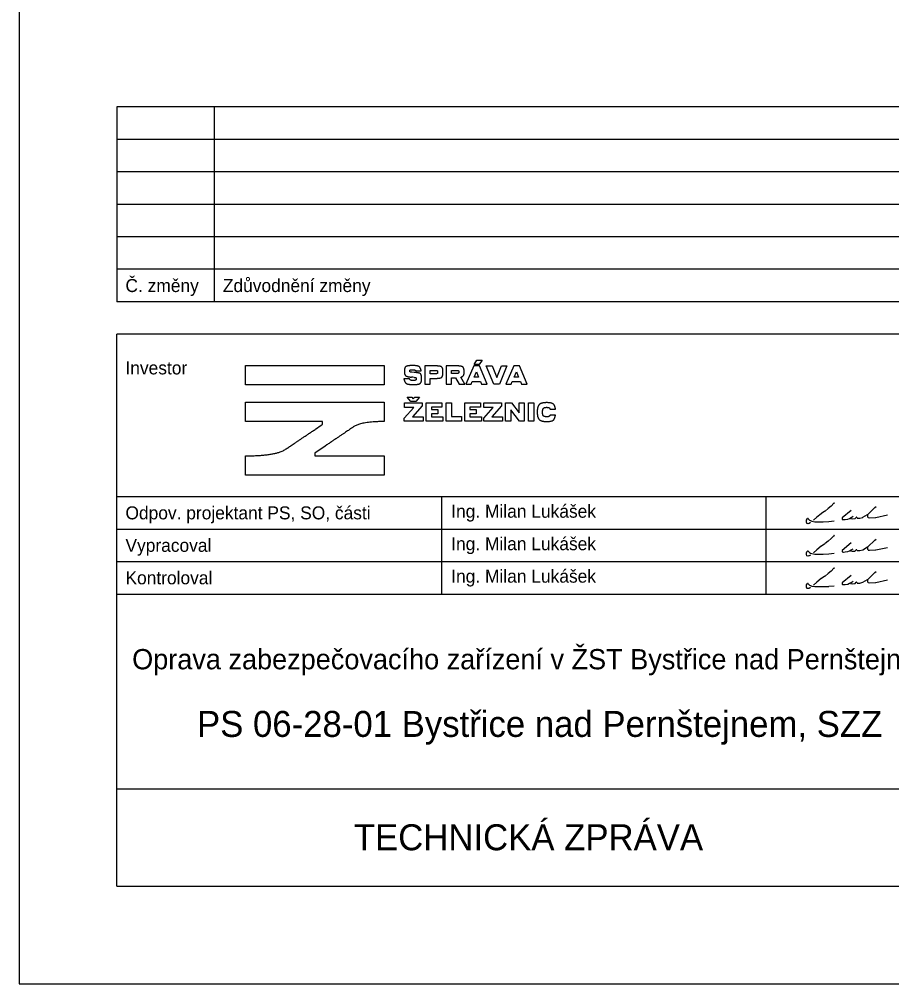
# Model space of a CAD drawing. Extents: x -790261 to -790051, y -987399 to -987102.
# Drawn here: x -790260.6 to -790126.2, y -987398.6 to -987250.1 of the extents above; entities that cross this region are included whole.
import ezdxf

# ---------------------------------------------------------------- set-up
doc = ezdxf.new("R2010")
doc.units = 0
for name, color, linetype in [('Deska žb', 7, 'Continuous'), ('logo_sprava_zeleznic', 7, 'Continuous'), ('Nová vrstva (0)', 7, 'Continuous'), ('Ramečky', 7, 'Continuous'), ('Rámečky-tisk', 7, 'Continuous'), ('Text', 7, 'Continuous'), ('Text barevný', 7, 'Continuous')]:
    doc.layers.add(name, color=color, linetype=linetype)

# ---------------------------------------------------------------- blocks, each defined once
blk = doc.blocks.new('Lukášek')
at = {"layer": 'Deska žb'}
for points in [[(-800, 511), (-947, 387)], [(-658, 623), (-799, 512)], [(-538, 757), (-656, 625)], [(-526, 763), (-532, 761)], [(-502, 743), (-503, 750)], [(1060, 236), (1392, 554)], [(1393, 555), (1452, 601)], [(-1810, -20), (-1764, 37)], [(-1741, 39), (-1734, 34)], [(-1733, 32), (-1676, -31)], [(-1334, 99), (-1493, -40)], [(-1120, 270), (-1334, 99)], [(-949, 386), (-1119, 271)], [(-146, 58), (-146, 41)], [(-146, 38), (-141, 12)], [(277, 422), (-140, 71)], [(0, 0), (116, 16)], [(120, 17), (203, 49)], [(205, 50), (283, 92)], [(244, 59), (250, 49)], [(261, 42), (331, 30)], [(284, 93), (373, 148)], [(335, 30), (465, 39)], [(476, 45), (519, 96)], [(546, 94), (559, 68)], [(574, 60), (681, 63)], [(685, 63), (829, 98)], [(833, 100), (1057, 233)], [(1056, 231), (1056, 130)], [(1058, 121), (1075, 95)], [(1086, 88), (1147, 79)], [(1150, 79), (1434, 92)], [(1437, 93), (1997, 211)], [(-1825, -119), (-1813, -28)], [(-1809, -179), (-1825, -126)], [(-1757, -200), (-1797, -190)], [(-1700, -189), (-1749, -201)], [(-1634, -152), (-1695, -187)], [(-1672, -34), (-1636, -56)], [(-1633, -57), (-1570, -82)], [(-1567, -83), (-1418, -106)], [(-1415, -106), (-1252, -106), (-1041, -106)], [(-1040, -106), (-770, -93)], [(-769, -92), (-512, -66)], [(-127, -2), (-88, -6)], [(-85, -7), (-1, 0)]]:
    blk.add_lwpolyline(points, dxfattribs=at)
for centre, start, end in [((-789, 499), 128.3333, 130.1792), ((-669, 636), 308.3333, 317.9357), ((-525, 746), 113.9625, 137.9357), ((-519, 748), 6.3402, 113.9625), ((1403, 542), 127.875, 133.8427), ((-1751, 26), 50.1944, 140.7106), ((-1745, 21), 41.9872, 50.1944), ((-1324, 86), 128.6598, 131.1859), ((-1110, 257), 123.9436, 128.6598), ((-958, 399), 303.9436, 310.1792), ((-129, 58), 130.156, 180), ((-129, 41), 180, 189.4623), ((-125, 15), 189.4623, 262.875), ((-2, 16), 274.3987, 277.9072), ((114, 32), 277.9072, 291.0375), ((197, 64), 291.0375, 298.4429), ((264, 58), 210.9638, 260.5377), ((275, 107), 298.4429, 302.1957), ((334, 46), 260.5377, 274.0856), ((463, 55), 274.0856, 320.4403), ((531, 86), 27.8973, 140.4403), ((574, 76), 207.8973, 271.5911), ((681, 79), 271.5911, 283.7363), ((825, 114), 283.7363, 300.7189), ((1072, 130), 180, 212.4712), ((1049, 247), 300.7189, 313.8427), ((1089, 104), 212.4712, 261.8699), ((1149, 96), 261.8699, 272.6324), ((1433, 109), 272.6324, 281.9566), ((-1809, -121), 172.4054, 196.6992), ((-1797, -30), 140.7106, 172.4054), ((-1793, -175), 196.6992, 255.9638), ((-1753, -184), 255.9638, 283.2405), ((-1703, -173), 283.2405, 300.0686), ((-1664, -20), 221.9872, 239.7436), ((-1627, -41), 239.7436, 248.1986), ((-1564, -67), 248.1986, 261.3475), ((-1415, -89), 261.3475, 270), ((-1041, -89), 270, 272.7927), ((-771, -76), 272.7927, 275.856), ((-86, 10), 262.875, 274.3987)]:
    blk.add_arc(centre, 16.5, start, end, dxfattribs=at)

msp = doc.modelspace()

# ---------------------------------------------------------------- linework, layer by layer
at = {"layer": 'logo_sprava_zeleznic'}
for p, q in [((-790190.56, -987303.26), (-790190.12, -987302.6)), ((-790189.78, -987303.26), (-790190.56, -987303.26)), ((-790190.12, -987302.6), (-790189.3, -987302.6)), ((-790189.3, -987302.6), (-790189.78, -987303.26)), ((-790188.7, -987303.48), (-790187.76, -987303.48)), ((-790187.49, -987306.29), (-790188.7, -987303.48)), ((-790187.76, -987303.48), (-790187.05, -987305.28)), ((-790187.05, -987305.28), (-790186.34, -987303.48)), ((-790185.49, -987303.48), (-790186.64, -987306.29)), ((-790186.34, -987303.48), (-790185.49, -987303.48)), ((-790199.76, -987304.48), (-790200.15, -987304.45)), ((-790199.51, -987304.23), (-790198.69, -987304.23)), ((-790200.51, -987305.45), (-790201.36, -987305.45)), ((-790186.64, -987306.29), (-790187.49, -987306.29)), ((-790201.26, -987309.17), (-790198.55, -987309.17)), ((-790201.26, -987309.86), (-790201.26, -987309.17)), ((-790200.29, -987308.96), (-790200.83, -987308.28)), ((-790200.83, -987308.28), (-790200.14, -987308.28)), ((-790199.53, -987308.96), (-790200.29, -987308.96)), ((-790200.14, -987308.28), (-790199.91, -987308.56)), ((-790198.55, -987309.63), (-790200.02, -987311.29)), ((-790199.91, -987308.56), (-790199.68, -987308.28)), ((-790199.68, -987308.28), (-790198.97, -987308.28)), ((-790198.97, -987308.28), (-790199.53, -987308.96)), ((-790198.55, -987309.17), (-790198.55, -987309.63)), ((-790197.92, -987309.17), (-790195.49, -987309.17)), ((-790197.92, -987311.99), (-790197.92, -987309.17)), ((-790195.49, -987309.17), (-790195.49, -987309.83)), ((-790194.86, -987309.17), (-790194.05, -987309.17)), ((-790194.86, -987311.99), (-790194.86, -987309.17)), ((-790194.05, -987309.17), (-790194.05, -987311.28)), ((-790191.99, -987309.17), (-790189.57, -987309.17)), ((-790191.99, -987311.99), (-790191.99, -987309.17)), ((-790189.57, -987309.17), (-790189.57, -987309.83)), ((-790189.03, -987309.17), (-790186.33, -987309.17)), ((-790189.03, -987309.86), (-790189.03, -987309.17)), ((-790186.33, -987309.63), (-790187.8, -987311.29)), ((-790186.33, -987309.17), (-790186.33, -987309.63)), ((-790185.69, -987309.17), (-790184.78, -987309.17)), ((-790185.69, -987311.99), (-790185.69, -987309.17)), ((-790184.78, -987309.17), (-790183.63, -987310.68)), ((-790183.63, -987310.68), (-790183.63, -987309.17)), ((-790183.63, -987309.17), (-790182.85, -987309.17)), ((-790182.85, -987309.17), (-790182.85, -987311.99)), ((-790201.3, -987311.53), (-790199.84, -987309.86)), ((-790199.84, -987309.86), (-790201.26, -987309.86)), ((-790195.49, -987309.83), (-790197.1, -987309.83)), ((-790197.1, -987309.83), (-790197.1, -987310.2)), ((-790197.1, -987310.2), (-790196.14, -987310.2)), ((-790196.14, -987310.87), (-790197.1, -987310.87)), ((-790197.1, -987310.87), (-790197.1, -987311.3)), ((-790196.14, -987310.2), (-790196.14, -987310.87)), ((-790189.57, -987309.83), (-790191.18, -987309.83)), ((-790191.18, -987309.83), (-790191.18, -987310.2)), ((-790191.18, -987310.2), (-790190.22, -987310.2)), ((-790190.22, -987310.87), (-790191.18, -987310.87)), ((-790191.18, -987310.87), (-790191.18, -987311.3)), ((-790190.22, -987310.2), (-790190.22, -987310.87)), ((-790189.07, -987311.53), (-790187.61, -987309.86)), ((-790187.61, -987309.86), (-790189.03, -987309.86)), ((-790183.53, -987311.99), (-790184.89, -987310.26)), ((-790184.89, -987310.26), (-790184.89, -987311.99)), ((-790178.84, -987310.12), (-790178.01, -987310.12)), ((-790178.01, -987311.05), (-790178.83, -987311.05)), ((-790201.3, -987311.99), (-790201.3, -987311.53)), ((-790198.39, -987311.99), (-790201.3, -987311.99)), ((-790200.02, -987311.29), (-790198.39, -987311.29)), ((-790198.39, -987311.29), (-790198.39, -987311.99)), ((-790195.34, -987311.99), (-790197.92, -987311.99)), ((-790197.1, -987311.3), (-790195.34, -987311.3)), ((-790195.34, -987311.3), (-790195.34, -987311.99)), ((-790192.47, -987311.99), (-790194.86, -987311.99)), ((-790194.05, -987311.28), (-790192.47, -987311.28)), ((-790192.47, -987311.28), (-790192.47, -987311.99)), ((-790189.41, -987311.99), (-790191.99, -987311.99)), ((-790191.18, -987311.3), (-790189.41, -987311.3)), ((-790189.41, -987311.3), (-790189.41, -987311.99)), ((-790189.07, -987311.99), (-790189.07, -987311.53)), ((-790186.16, -987311.99), (-790189.07, -987311.99)), ((-790187.8, -987311.29), (-790186.16, -987311.29)), ((-790186.16, -987311.29), (-790186.16, -987311.99)), ((-790184.89, -987311.99), (-790185.69, -987311.99)), ((-790182.85, -987311.99), (-790183.53, -987311.99))]:
    msp.add_line(p, q, dxfattribs=at)
for points in [[(-790225.73, -987303.4), (-790204.41, -987303.4), (-790204.41, -987306.38), (-790225.73, -987306.38)], [(-790191.8, -987306.29), (-790190.98, -987306.29), (-790190.82, -987305.89), (-790189.57, -987305.89), (-790189.41, -987306.29), (-790188.53, -987306.29), (-790189.73, -987303.48), (-790190.6, -987303.48)], [(-790185.65, -987306.29), (-790184.83, -987306.29), (-790184.66, -987305.89), (-790183.42, -987305.89), (-790183.26, -987306.29), (-790182.38, -987306.29), (-790183.57, -987303.48), (-790184.45, -987303.48)], [(-790190.19, -987304.39), (-790189.85, -987305.23), (-790190.54, -987305.23)], [(-790184.04, -987304.39), (-790183.7, -987305.23), (-790184.39, -987305.23)], [(-790182.16, -987309.17), (-790181.35, -987309.17), (-790181.35, -987311.99), (-790182.16, -987311.99)]]:
    msp.add_lwpolyline(points, close=True, dxfattribs=at)
for points in [[(-790196.38, -987303.48), (-790198.11, -987303.48), (-790198.11, -987306.29), (-790197.3, -987306.29), (-790197.3, -987305.39), (-790196.38, -987305.39)], [(-790193.12, -987303.48), (-790194.84, -987303.48), (-790194.84, -987306.29), (-790194.03, -987306.29), (-790194.03, -987305.31), (-790193.39, -987305.31), (-790192.84, -987306.29), (-790191.98, -987306.29), (-790192.59, -987305.22)], [(-790196.48, -987304.69), (-790197.3, -987304.69), (-790197.3, -987304.17), (-790196.48, -987304.17)], [(-790193.22, -987304.64), (-790194.03, -987304.64), (-790194.03, -987304.16), (-790193.22, -987304.16)], [(-790213.87, -987312.46), (-790213.87, -987312.04), (-790225.73, -987312.04), (-790225.73, -987309.07), (-790204.41, -987309.07), (-790204.41, -987312.04)], [(-790215.1, -987316.91), (-790215.1, -987317.32), (-790204.41, -987317.32), (-790204.41, -987320.3), (-790225.73, -987320.3), (-790225.73, -987317.32), (-790225.71, -987317.32)]]:
    msp.add_lwpolyline(points, dxfattribs=at)
for centre, radius, start, end in [((-790201.9, -987326.14), 21.01, 84.2634, 85.3384), ((-790251.18, -987259.6), 64.69, 304.0901, 305.2133), ((-789914.63, -987753.54), 530.02, 124.292, 124.5333)]:
    msp.add_arc(centre, radius, start, end, dxfattribs=at)
for points in [[(-790200.05, -987303.42), (-790200.77, -987303.42), (-790201.29, -987303.71), (-790201.29, -987304.28)], [(-790198.69, -987304.23), (-790198.77, -987303.87), (-790199.09, -987303.42), (-790200.05, -987303.42)], [(-790195.34, -987304.43), (-790195.34, -987303.8), (-790195.73, -987303.48), (-790196.38, -987303.48)], [(-790192.08, -987304.4), (-790192.08, -987303.79), (-790192.49, -987303.48), (-790193.12, -987303.48)], [(-790201.29, -987304.28), (-790201.29, -987304.83), (-790200.87, -987305.14), (-790200.19, -987305.2)], [(-790200.46, -987304.24), (-790200.46, -987304.12), (-790200.3, -987304.06), (-790200.05, -987304.06)], [(-790200.15, -987304.45), (-790200.35, -987304.43), (-790200.46, -987304.36), (-790200.46, -987304.24)], [(-790200.05, -987304.06), (-790199.73, -987304.06), (-790199.55, -987304.17), (-790199.51, -987304.23)], [(-790198.63, -987305.4), (-790198.63, -987304.79), (-790199.03, -987304.53), (-790199.76, -987304.48)], [(-790196.48, -987304.17), (-790196.27, -987304.17), (-790196.17, -987304.26), (-790196.17, -987304.43)], [(-790196.17, -987304.43), (-790196.17, -987304.59), (-790196.27, -987304.69), (-790196.48, -987304.69)], [(-790196.38, -987305.39), (-790195.73, -987305.39), (-790195.34, -987305.06), (-790195.34, -987304.43)], [(-790193.22, -987304.16), (-790193.02, -987304.16), (-790192.91, -987304.23), (-790192.91, -987304.4)], [(-790192.91, -987304.4), (-790192.91, -987304.55), (-790193.02, -987304.64), (-790193.22, -987304.64)], [(-790192.59, -987305.22), (-790192.27, -987305.08), (-790192.08, -987304.8), (-790192.08, -987304.4)], [(-790201.36, -987305.45), (-790201.29, -987305.84), (-790200.93, -987306.34), (-790199.92, -987306.34)], [(-790199.92, -987305.71), (-790200.28, -987305.71), (-790200.46, -987305.57), (-790200.51, -987305.45)], [(-790199.92, -987306.34), (-790199.08, -987306.34), (-790198.63, -987306), (-790198.63, -987305.4)], [(-790199.47, -987305.46), (-790199.47, -987305.61), (-790199.6, -987305.71), (-790199.92, -987305.71)], [(-790199.8, -987305.23), (-790199.6, -987305.26), (-790199.47, -987305.31), (-790199.47, -987305.46)], [(-790179.36, -987309.13), (-790180.22, -987309.13), (-790180.82, -987309.73), (-790180.82, -987310.58)], [(-790178.01, -987310.12), (-790178.06, -987309.8), (-790178.4, -987309.13), (-790179.36, -987309.13)], [(-790180.82, -987310.58), (-790180.82, -987311.43), (-790180.22, -987312.04), (-790179.36, -987312.04)], [(-790180, -987310.58), (-790180, -987310.18), (-790179.76, -987309.85), (-790179.36, -987309.85)], [(-790179.36, -987311.31), (-790179.76, -987311.31), (-790180, -987310.99), (-790180, -987310.58)], [(-790179.36, -987309.85), (-790179.02, -987309.85), (-790178.88, -987310.05), (-790178.84, -987310.12)], [(-790179.36, -987312.04), (-790178.37, -987312.04), (-790178.05, -987311.31), (-790178.01, -987311.05)], [(-790178.83, -987311.05), (-790178.87, -987311.12), (-790179.02, -987311.31), (-790179.36, -987311.31)], [(-790204.41, -987312.04), (-790207.9, -987312.04), (-790210.38, -987313.71), (-790213.25, -987315.65)], [(-790225.71, -987317.32), (-790221.06, -987317.31), (-790218.08, -987315.3), (-790214.92, -987313.18)]]:
    msp.add_open_spline(points, degree=2, dxfattribs=at)
at = {"layer": 'Ramečky'}
for p, q in [((-790065.59, -987263.6), (-790245.59, -987263.6)), ((-790245.59, -987263.6), (-790245.59, -987293.6)), ((-790230.59, -987263.6), (-790230.59, -987293.6)), ((-790095.59, -987268.6), (-790245.59, -987268.6)), ((-790095.59, -987273.6), (-790245.59, -987273.6)), ((-790095.59, -987278.6), (-790245.59, -987278.6)), ((-790095.59, -987283.6), (-790245.59, -987283.6)), ((-790095.59, -987288.6), (-790245.59, -987288.6)), ((-790065.59, -987293.6), (-790245.59, -987293.6)), ((-790065.59, -987298.6), (-790245.59, -987298.6)), ((-790245.59, -987383.6), (-790245.59, -987298.6)), ((-790245.59, -987323.6), (-790115.59, -987323.6)), ((-790245.59, -987328.6), (-790115.59, -987328.6)), ((-790245.59, -987333.6), (-790115.59, -987333.6)), ((-790245.59, -987338.6), (-790115.59, -987338.6)), ((-790245.59, -987368.6), (-790065.59, -987368.6)), ((-790245.59, -987383.6), (-790065.59, -987383.6))]:
    msp.add_line(p, q, dxfattribs=at)
for points in [[(-790195.59, -987323.6), (-790195.59, -987338.6)], [(-790145.59, -987323.6), (-790145.59, -987338.6)]]:
    msp.add_lwpolyline(points, dxfattribs=at)
at = {"layer": 'Rámečky-tisk'}
msp.add_line((-790260.59, -987101.6), (-790260.59, -987398.6), dxfattribs=at)
msp.add_lwpolyline([(-790260.59, -987398.6), (-790050.59, -987398.6), (-790050.59, -987101.6)], dxfattribs=at)

# ---------------------------------------------------------------- block references
at = {"layer": 'Nová vrstva (0)', "xscale": 0.00327555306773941, "yscale": 0.00327555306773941}
for p in [(-790133.4, -987327.11), (-790133.4, -987332.11), (-790133.4, -987337.11)]:
    msp.add_blockref('Lukášek', p, dxfattribs=at)

# ---------------------------------------------------------------- texts
at = {"layer": 'Text'}
for s, p in [('Č. změny', (-790244.24, -987292.1)), ('Zdůvodnění změny', (-790229.24, -987292.1)), ('Investor', (-790244.24, -987304.78)), ('Odpov. projektant PS, SO, části', (-790244.24, -987327.1)), ('Ing. Milan Lukášek', (-790194.07, -987326.85)), ('Vypracoval', (-790244.24, -987332.1)), ('Ing. Milan Lukášek', (-790194.07, -987331.85)), ('Ing. Milan Lukášek', (-790194.07, -987336.85)), ('Kontroloval', (-790244.24, -987337.1))]:
    msp.add_text(s, height=2, dxfattribs=at).set_placement(p)
at = {"layer": 'Text barevný'}
for s, height, p in [('Oprava zabezpečovacího zařízení v ŽST Bystřice nad Pernštejnem', 3.1179, (-790243.21, -987350.19)), ('PS 06-28-01 Bystřice nad Pernštejnem, SZZ', 4, (-790233.22, -987360.6)), ('TECHNICKÁ ZPRÁVA', 4, (-790209.07, -987378.05))]:
    msp.add_text(s, height=height, dxfattribs=at).set_placement(p)

doc.saveas('drawing.dxf')
